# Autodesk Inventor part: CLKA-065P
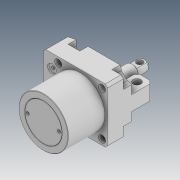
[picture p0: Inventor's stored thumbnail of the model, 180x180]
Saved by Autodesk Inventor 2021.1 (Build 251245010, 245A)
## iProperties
Created: 2018-07
Part Number: CLKA-065P
Material: Ogólny
Description: STEP AP203
Document SubType Name: Modeling
Designer: user
Density: 1 g/cm^3
Appearance: Domyślna
Title: CLKA-065P.STEP
Revision Number: ÈÎºÎ
Sending System: SolidWorks 2015
Preprocessor: SwSTEP 2.0
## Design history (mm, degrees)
feature "ÇÐ³ý-À­Éì10"
node "Bryła1"
